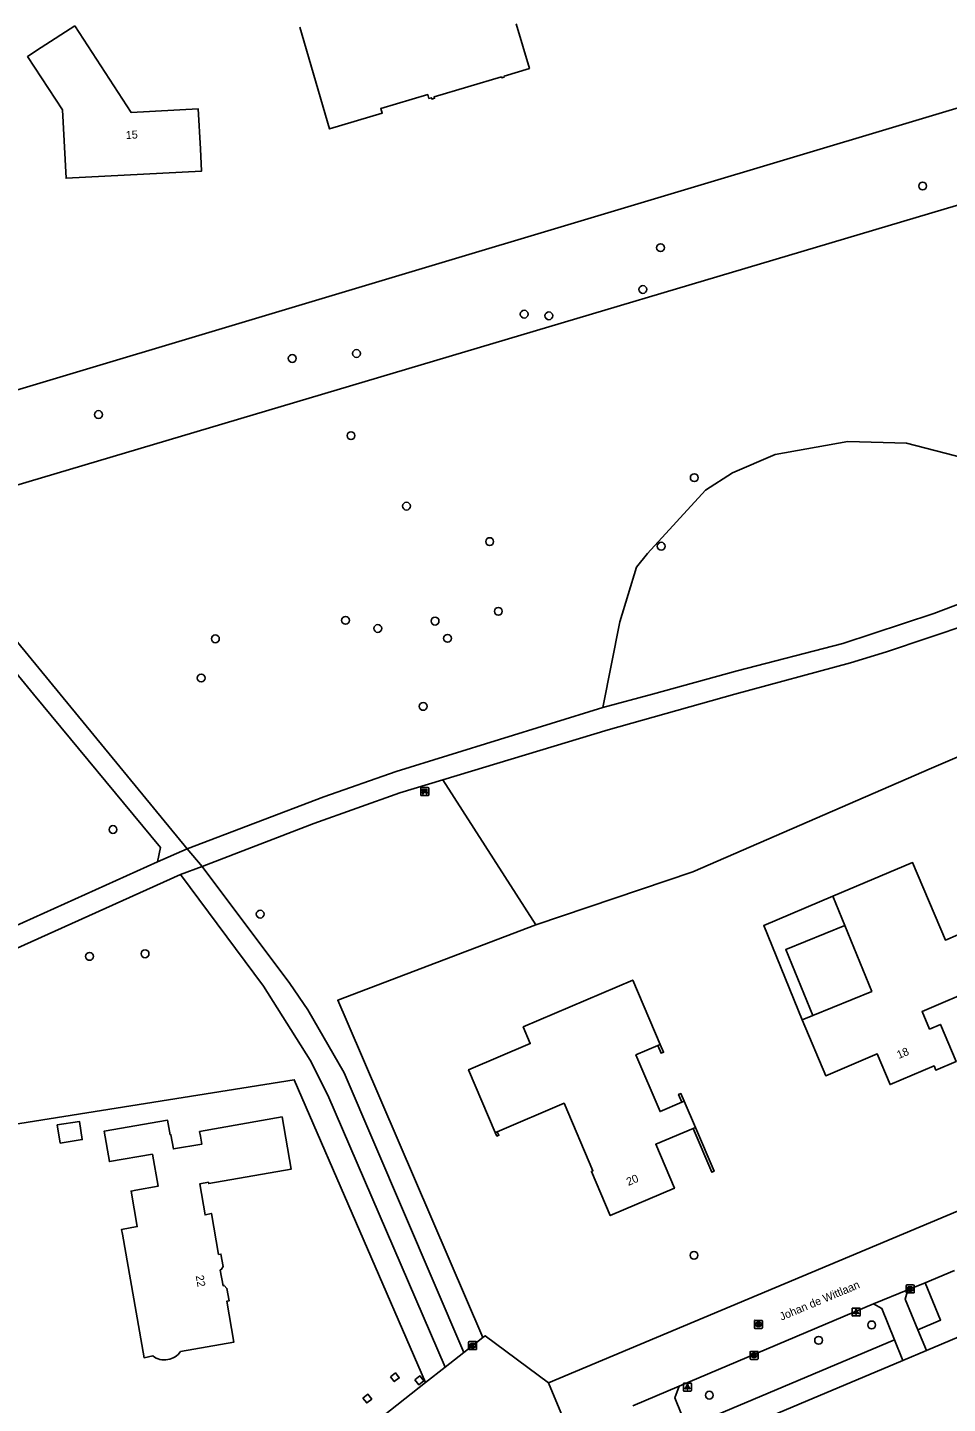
# Model space of a CAD drawing. Extents: x 162417 to 163721, y 384268 to 385416.
# Drawn here: x 163118.6 to 163233.5, y 384911.4 to 385083.3 of the extents above; entities that cross this region are included whole.
import ezdxf

# ---------------------------------------------------------------- set-up
doc = ezdxf.new("R2010")
doc.units = 0
for name, color, linetype in [('IMGEO_Bank', 7, 'Continuous'), ('IMGEO_Boom', 7, 'Continuous'), ('IMGEO_Erf', 7, 'Continuous'), ('IMGEO_Gemengd_bos', 7, 'Continuous'), ('IMGEO_Groenvoorziening', 7, 'Continuous'), ('IMGEO_Kolk', 7, 'Continuous'), ('IMGEO_Lichtpunt', 7, 'Continuous'), ('IMGEO_Loofbos', 7, 'Continuous'), ('IMGEO_Muur', 7, 'Continuous'), ('IMGEO_Openbare_ruimte_label', 7, 'Continuous'), ('IMGEO_Pand', 7, 'Continuous'), ('IMGEO_Pand_nummerreeks', 7, 'Continuous'), ('IMGEO_Pand_vergunning_verleend', 7, 'Continuous'), ('IMGEO_Rijbaan_lokaal_gesloten', 7, 'Continuous'), ('IMGEO_Rioolput', 7, 'Continuous'), ('IMGEO_Voetpad_halfverhard', 7, 'Continuous'), ('IMGEO_Voetpad_open', 7, 'Continuous')]:
    doc.layers.add(name, color=color, linetype=linetype)

msp = doc.modelspace()

# ---------------------------------------------------------------- linework, layer by layer
at = {"layer": 'IMGEO_Bank'}
for p, q in [((163167.7, 384987.41), (163167.7, 384988.25)), ((163167.7, 384988.25), (163167.7, 384987.41)), ((163167.78, 384988.34), (163168.62, 384988.34)), ((163168.62, 384988.34), (163167.78, 384988.34)), ((163168.63, 384987.34), (163167.79, 384987.34)), ((163167.79, 384987.34), (163168.63, 384987.34)), ((163168.01, 384987.85), (163168.01, 384987.95)), ((163168.4, 384987.74), (163168.01, 384987.74)), ((163168.34, 384987.96), (163168.06, 384987.96)), ((163168.06, 384987.95), (163168.06, 384987.85)), ((163168.06, 384987.84), (163168.34, 384987.84)), ((163168.35, 384987.85), (163168.35, 384987.95)), ((163168.39, 384987.95), (163168.39, 384987.85)), ((163168.7, 384988.26), (163168.7, 384987.42)), ((163168.7, 384987.42), (163168.7, 384988.26))]:
    msp.add_line(p, q, dxfattribs=at)
for points in [[(163167.95, 384987.74), (163167.81, 384987.74), (163167.92, 384987.84), (163168.01, 384987.84)], [(163168.01, 384987.96), (163167.92, 384987.96), (163167.92, 384988.12), (163168.48, 384988.12), (163168.48, 384987.96), (163168.4, 384987.96)], [(163168, 384987.73), (163168, 384987.52), (163167.96, 384987.52), (163167.96, 384987.73)], [(163168.4, 384987.84), (163168.48, 384987.84), (163168.6, 384987.74), (163168.46, 384987.74)], [(163168.45, 384987.73), (163168.45, 384987.52), (163168.41, 384987.52), (163168.41, 384987.73)]]:
    msp.add_lwpolyline(points, dxfattribs=at)
for centre, radius, start, end in [((163167.78, 384988.26), 0.0779, 92.4484, 184.2845), ((163167.78, 384988.26), 0.0779, 92.4484, 184.2845), ((163167.78, 384987.42), 0.0779, 182.4484, 274.2845), ((163167.78, 384987.42), 0.0779, 182.4484, 274.2845), ((163167.95, 384987.73), 0.00671, 2.8957, 87.1043), ((163168.01, 384987.73), 0.00671, 92.8957, 177.1043), ((163168.01, 384987.95), 0.00671, 2.8957, 87.1043), ((163168.01, 384987.85), 0.00671, 272.8957, 357.1043), ((163168.06, 384987.95), 0.00671, 92.8957, 177.1043), ((163168.06, 384987.85), 0.00671, 182.8957, 267.1043), ((163168.34, 384987.95), 0.00671, 2.8957, 87.1043), ((163168.34, 384987.85), 0.00671, 272.8957, 357.1043), ((163168.4, 384987.95), 0.00671, 92.8957, 177.1043), ((163168.4, 384987.85), 0.00671, 182.8957, 267.1043), ((163168.4, 384987.73), 0.00671, 2.8957, 87.1043), ((163168.46, 384987.73), 0.00671, 92.8957, 177.1043), ((163168.63, 384988.26), 0.0779, 2.4484, 94.2845), ((163168.63, 384988.26), 0.0779, 2.4484, 94.2845), ((163168.63, 384987.42), 0.0779, 272.4484, 4.2845), ((163168.63, 384987.42), 0.0779, 272.4484, 4.2845)]:
    msp.add_arc(centre, radius, start, end, dxfattribs=at)
at = {"layer": 'IMGEO_Boom'}
for centre in [(163230.43, 385063.49), (163197.68, 385055.79), (163195.47, 385050.57), (163180.64, 385047.48), (163183.72, 385047.28), (163151.65, 385041.95), (163159.68, 385042.57), (163127.44, 385034.94), (163158.99, 385032.31), (163201.89, 385027.05), (163165.93, 385023.5), (163176.32, 385019.07), (163197.76, 385018.49), (163158.31, 385009.23), (163169.5, 385009.14), (163177.4, 385010.36), (163162.34, 385008.22), (163142.05, 385006.93), (163171.06, 385006.98), (163140.27, 385002.03), (163168.02, 384998.48), (163129.25, 384983.1), (163147.65, 384972.53), (163126.32, 384967.25), (163133.26, 384967.58), (163201.86, 384929.91), (163224.06, 384921.21), (163217.43, 384919.29), (163203.78, 384912.43)]:
    msp.add_circle(centre, 0.489, dxfattribs=at)
at = {"layer": 'IMGEO_Erf'}
for points in [[(163215.38, 384959.32), (163210.57, 384971.11), (163219.21, 384974.77)], [(163216.7, 384959.86), (163213.33, 384968.12), (163220.69, 384971.13)], [(163163.93, 384914.74), (163164.55, 384915.21), (163165.02, 384914.6), (163164.4, 384914.13), (163163.93, 384914.74)], [(163166.99, 384914.36), (163167.6, 384914.84), (163168.09, 384914.23), (163167.47, 384913.74), (163166.99, 384914.36)], [(163160.49, 384912.08), (163161.1, 384912.56), (163161.58, 384911.94), (163160.97, 384911.47), (163160.49, 384912.08)]]:
    msp.add_lwpolyline(points, dxfattribs=at)
at = {"layer": 'IMGEO_Gemengd_bos'}
for points in [[(163109.64, 385035.76), (163200.68, 385063.02), (163281.97, 385087.41)], [(163104.31, 385022.27), (163286.02, 385076.36)], [(163277.36, 385010.29), (163269.66, 385007.07), (163253.07, 385000), (163231.53, 384990.76), (163201.72, 384977.8), (163182.1, 384971.2)], [(163170.48, 384989.3), (163182.1, 384971.2)], [(163182.1, 384971.2), (163157.34, 384961.78), (163158.51, 384959.07), (163175.47, 384919.62)]]:
    msp.add_lwpolyline(points, dxfattribs=at)
at = {"layer": 'IMGEO_Groenvoorziening'}
msp.add_lwpolyline([(163190.46, 384998.35), (163192.6, 385009.04), (163194.69, 385015.88), (163196.06, 385017.57), (163203.31, 385025.48), (163206.68, 385027.67), (163212, 385029.94), (163221.1, 385031.58), (163228.41, 385031.37), (163249.98, 385025.8), (163256.09, 385024.66), (163270.81, 385024.87)], dxfattribs=at)
at = {"layer": 'IMGEO_Kolk'}
for p, q in [((163228.38, 384925.28), (163228.38, 384926.13)), ((163228.46, 384926.21), (163229.31, 384926.21)), ((163228.87, 384925.99), (163228.89, 384925.99)), ((163228.89, 384925.43), (163228.87, 384925.43)), ((163229.38, 384926.13), (163229.38, 384925.28)), ((163229.31, 384925.21), (163228.46, 384925.21)), ((163173.69, 384918.2), (163173.69, 384919.05)), ((163173.76, 384919.13), (163174.62, 384919.13)), ((163174.18, 384918.91), (163174.2, 384918.91)), ((163174.69, 384919.05), (163174.69, 384918.2)), ((163174.62, 384918.13), (163173.76, 384918.13)), ((163174.2, 384918.35), (163174.18, 384918.35)), ((163208.86, 384916.99), (163208.86, 384917.84)), ((163208.94, 384917.91), (163209.79, 384917.91)), ((163209.79, 384916.91), (163208.94, 384916.91)), ((163209.35, 384917.69), (163209.38, 384917.69)), ((163209.37, 384917.13), (163209.35, 384917.13)), ((163209.86, 384917.84), (163209.86, 384916.99))]:
    msp.add_line(p, q, dxfattribs=at)
for points in [[(163228.38, 384925.28), (163228.38, 384926.13)], [(163228.46, 384926.21), (163229.31, 384926.21)], [(163228.7, 384925.91), (163228.83, 384925.91), (163228.83, 384925.76), (163228.95, 384925.91), (163229.12, 384925.91), (163228.97, 384925.76), (163229.13, 384925.51), (163228.97, 384925.51), (163228.89, 384925.67), (163228.83, 384925.6), (163228.83, 384925.51), (163228.7, 384925.51), (163228.7, 384925.91)], [(163229.38, 384926.13), (163229.38, 384925.28)], [(163229.31, 384925.21), (163228.46, 384925.21)], [(163173.69, 384918.2), (163173.69, 384919.05)], [(163173.76, 384919.13), (163174.62, 384919.13)], [(163174.01, 384918.83), (163174.13, 384918.83), (163174.13, 384918.67), (163174.26, 384918.83), (163174.43, 384918.83), (163174.28, 384918.68), (163174.43, 384918.43), (163174.28, 384918.43), (163174.2, 384918.59), (163174.13, 384918.52), (163174.13, 384918.43), (163174.01, 384918.43), (163174.01, 384918.83)], [(163174.69, 384919.05), (163174.69, 384918.2)], [(163174.62, 384918.13), (163173.76, 384918.13)], [(163208.86, 384916.99), (163208.86, 384917.84)], [(163208.94, 384917.91), (163209.79, 384917.91)], [(163209.79, 384916.91), (163208.94, 384916.91)], [(163209.18, 384917.61), (163209.31, 384917.61), (163209.31, 384917.46), (163209.44, 384917.61), (163209.6, 384917.61), (163209.45, 384917.46), (163209.61, 384917.21), (163209.45, 384917.21), (163209.37, 384917.38), (163209.31, 384917.31), (163209.31, 384917.21), (163209.18, 384917.21), (163209.18, 384917.61)], [(163209.86, 384917.84), (163209.86, 384916.99)]]:
    msp.add_lwpolyline(points, dxfattribs=at)
for centre, start, end in [((163228.46, 384926.13), 91.552, 178.448), ((163228.46, 384926.13), 91.552, 178.448), ((163229.31, 384926.13), 1.552, 88.448), ((163229.31, 384926.13), 1.552, 88.448), ((163228.46, 384925.28), 181.552, 268.448), ((163228.46, 384925.28), 181.552, 268.448), ((163229.31, 384925.28), 271.552, 358.448), ((163229.31, 384925.28), 271.552, 358.448), ((163173.77, 384919.05), 91.552, 178.448), ((163173.77, 384919.05), 91.552, 178.448), ((163174.61, 384919.05), 1.552, 88.448), ((163174.61, 384919.05), 1.552, 88.448), ((163173.77, 384918.2), 181.552, 268.448), ((163173.77, 384918.2), 181.552, 268.448), ((163174.61, 384918.2), 271.552, 358.448), ((163174.61, 384918.2), 271.552, 358.448), ((163208.94, 384917.84), 91.552, 178.448), ((163208.94, 384917.84), 91.552, 178.448), ((163208.94, 384916.99), 181.552, 268.448), ((163208.94, 384916.99), 181.552, 268.448), ((163209.79, 384917.84), 1.552, 88.448), ((163209.79, 384917.84), 1.552, 88.448), ((163209.79, 384916.99), 271.552, 358.448), ((163209.79, 384916.99), 271.552, 358.448)]:
    msp.add_arc(centre, 0.0765, start, end, dxfattribs=at)
for centre, major_axis, ratio, start_param, end_param in [((163228.87, 384925.71), (-0.387, 0.002), 0.722429, 4.712389, 7.853982), ((163228.89, 384925.71), (-0.39, 0.002), 0.717154, 1.570796, 4.712389), ((163174.18, 384918.63), (-0.387, 0.002), 0.722429, 4.712389, 7.853982), ((163174.2, 384918.63), (-0.39, 0.002), 0.717154, 1.570796, 4.712389), ((163209.35, 384917.41), (-0.387, 0.002), 0.722429, 4.712389, 7.853982), ((163209.37, 384917.41), (-0.39, 0.002), 0.717154, 1.570796, 4.712389)]:
    msp.add_ellipse(centre, major_axis=major_axis, ratio=ratio, start_param=start_param, end_param=end_param, dxfattribs=at)
at = {"layer": 'IMGEO_Lichtpunt'}
for p, q in [((163221.62, 384923.23), (163221.62, 384922.42)), ((163221.62, 384923.23), (163221.62, 384922.42)), ((163222.52, 384923.32), (163221.71, 384923.32)), ((163222.52, 384923.32), (163221.71, 384923.32)), ((163221.71, 384922.33), (163222.52, 384922.33)), ((163221.71, 384922.33), (163222.52, 384922.33)), ((163222.61, 384922.42), (163222.61, 384923.23)), ((163222.61, 384922.42), (163222.61, 384923.23)), ((163200.54, 384913.85), (163200.54, 384913.04)), ((163200.54, 384913.85), (163200.54, 384913.04)), ((163201.44, 384913.94), (163200.63, 384913.94)), ((163201.44, 384913.94), (163200.63, 384913.94)), ((163201.53, 384913.04), (163201.53, 384913.85)), ((163201.53, 384913.04), (163201.53, 384913.85)), ((163200.63, 384912.95), (163201.44, 384912.95)), ((163200.63, 384912.95), (163201.44, 384912.95))]:
    msp.add_line(p, q, dxfattribs=at)
for points in [[(163221.99, 384922.89), (163222.03, 384922.86), (163221.84, 384922.6), (163221.8, 384922.63), (163221.99, 384922.89)], [(163222.09, 384922.84), (163222.14, 384922.84), (163222.14, 384922.52), (163222.09, 384922.52), (163222.09, 384922.84)], [(163222.2, 384922.86), (163222.24, 384922.89), (163222.43, 384922.63), (163222.39, 384922.6), (163222.2, 384922.86)], [(163200.91, 384913.51), (163200.95, 384913.49), (163200.76, 384913.22), (163200.72, 384913.25), (163200.91, 384913.51)], [(163201.01, 384913.47), (163201.06, 384913.47), (163201.06, 384913.14), (163201.01, 384913.14), (163201.01, 384913.47)], [(163201.12, 384913.49), (163201.16, 384913.51), (163201.35, 384913.25), (163201.31, 384913.22), (163201.12, 384913.49)]]:
    msp.add_lwpolyline(points, dxfattribs=at)
for centre in [(163222.12, 384923.03), (163201.04, 384913.65)]:
    msp.add_circle(centre, 0.0994, dxfattribs=at)
for centre, start, end in [((163221.71, 384923.23), 90, 180), ((163221.71, 384923.23), 90, 180), ((163221.71, 384922.42), 180, 270), ((163221.71, 384922.42), 180, 270), ((163222.52, 384923.23), 0, 90), ((163222.52, 384923.23), 0, 90), ((163222.52, 384922.42), 270, 0), ((163222.52, 384922.42), 270, 360), ((163200.63, 384913.85), 90, 180), ((163200.63, 384913.85), 90, 180), ((163201.44, 384913.85), 0, 90), ((163201.44, 384913.85), 0, 90), ((163200.63, 384913.04), 180, 270), ((163200.63, 384913.04), 180, 270), ((163201.44, 384913.04), 270, 0), ((163201.44, 384913.04), 270, 360)]:
    msp.add_arc(centre, 0.0946, start, end, dxfattribs=at)
at = {"layer": 'IMGEO_Loofbos'}
msp.add_lwpolyline([(163168.29, 384914), (163151.9, 384951.84), (163097.15, 384943.13), (163103.62, 384899.24), (163109.03, 384862.7), (163116.8, 384810.17), (163172.67, 384818.52)], dxfattribs=at)
at = {"layer": 'IMGEO_Muur'}
for points in [[(163197.34, 384956.11), (163197.75, 384955.15), (163198.05, 384955.27), (163197.64, 384956.24)], [(163200.64, 384949.16), (163200.23, 384950.12), (163199.94, 384950), (163200.35, 384949.03)], [(163177.03, 384945.23), (163177.22, 384944.8), (163177.47, 384944.91), (163177.28, 384945.34)], [(163201.74, 384945.76), (163204.07, 384940.29), (163204.37, 384940.42), (163202.04, 384945.89)]]:
    msp.add_lwpolyline(points, dxfattribs=at)
at = {"layer": 'IMGEO_Pand'}
for points in [[(163124.48, 385083.5), (163131.52, 385072.68), (163139.91, 385073.12), (163140.17, 385068.13), (163140.32, 385065.36), (163123.38, 385064.46), (163122.93, 385072.99), (163118.58, 385079.67), (163120.29, 385080.78), (163124.48, 385083.5)], [(163179.64, 385083.75), (163181.3, 385078.18), (163178.14, 385077.23), (163178.17, 385077.12), (163177.83, 385077.02), (163177.8, 385077.13), (163169.38, 385074.63), (163169.43, 385074.46), (163169.08, 385074.36), (163169.04, 385074.52), (163168.73, 385074.43), (163168.58, 385074.91), (163162.72, 385073.16), (163162.89, 385072.59), (163156.31, 385070.62), (163152.58, 385083.32)], [(163219.21, 384974.77), (163229.17, 384978.98), (163233.27, 384969.28), (163234.83, 384969.94), (163237.58, 384963.43), (163230.37, 384960.38), (163231.3, 384958.18), (163232.66, 384958.75), (163234.62, 384954.11), (163232.08, 384953.04), (163231.86, 384953.56), (163226.37, 384951.24), (163224.75, 384955.07), (163218.33, 384952.35), (163215.38, 384959.32)], [(163219.21, 384974.77), (163220.69, 384971.13)], [(163220.69, 384971.13), (163224.07, 384962.87), (163216.7, 384959.86)], [(163197.64, 384956.24), (163194.21, 384964.29), (163180.51, 384958.45), (163181.4, 384956.36), (163173.69, 384953.08), (163177.03, 384945.23)], [(163216.7, 384959.86), (163215.38, 384959.32)], [(163200.35, 384949.03), (163197.62, 384947.87), (163194.61, 384954.95), (163197.34, 384956.11)], [(163197.64, 384956.24), (163197.34, 384956.11)], [(163177.28, 384945.34), (163185.63, 384948.9), (163189.22, 384940.47), (163189.04, 384940.39), (163191.39, 384934.87), (163199.42, 384938.29), (163197.08, 384943.78), (163201.74, 384945.76)], [(163200.35, 384949.03), (163200.64, 384949.16)], [(163202.04, 384945.89), (163200.64, 384949.16)], [(163134.24, 384917.33), (163133.14, 384917.12), (163130.43, 384932.54), (163130.32, 384933.15), (163132.29, 384933.5), (163131.51, 384937.93), (163132.11, 384938.04), (163134.89, 384938.53), (163134.18, 384942.53), (163128.8, 384941.61), (163128.15, 384945.42), (163136.08, 384946.78), (163136.39, 384944.96), (163136.49, 384944.98), (163136.8, 384943.19), (163140.34, 384943.79), (163140.17, 384944.78), (163140.07, 384945.37), (163150.39, 384947.19), (163151.53, 384940.69), (163141.21, 384938.87), (163141.17, 384939.03), (163140.11, 384938.85), (163140.76, 384934.95), (163141.54, 384935.14), (163142.45, 384930.01), (163142.74, 384930.06), (163143.02, 384928.53), (163142.83, 384928.17), (163142.66, 384928.06), (163143.01, 384926.11), (163143.16, 384926.14), (163143.49, 384925.78), (163143.77, 384924.23), (163143.48, 384924.2), (163144.36, 384919.07), (163137.7, 384917.91)], [(163177.28, 384945.34), (163177.03, 384945.23)], [(163202.04, 384945.89), (163201.74, 384945.76)]]:
    msp.add_lwpolyline(points, dxfattribs=at)
msp.add_arc((163135.7, 384919.24), 2.4, 232.4077, 326.3293, dxfattribs=at)
at = {"layer": 'IMGEO_Pand_vergunning_verleend'}
msp.add_lwpolyline([(163122.29, 384946.2), (163125.05, 384946.64), (163125.41, 384944.37), (163122.66, 384943.93), (163122.29, 384946.2)], dxfattribs=at)
at = {"layer": 'IMGEO_Rijbaan_lokaal_gesloten'}
for points in [[(163183.67, 384913.96), (163328.96, 384974.96)], [(163230.74, 384926.48), (163234.4, 384928)], [(163224.3, 384923.83), (163228.59, 384925.58)], [(163228.59, 384925.58), (163230.74, 384926.48)], [(163200.02, 384913.55), (163224.3, 384923.83)], [(163173.11, 384917.78), (163175.47, 384919.62)], [(163175.47, 384919.62), (163175.76, 384919.85), (163183.67, 384913.96)], [(163170.76, 384915.95), (163173.11, 384917.78)], [(163168.29, 384914), (163170.76, 384915.95)], [(163172.67, 384818.52), (163159.56, 384907.09), (163168.29, 384914)], [(163183.67, 384913.96), (163186.27, 384907.76)], [(163194.23, 384911.1), (163200.02, 384913.55)]]:
    msp.add_lwpolyline(points, dxfattribs=at)
at = {"layer": 'IMGEO_Rioolput'}
for p, q in [((163209.42, 384920.86), (163209.42, 384921.71)), ((163209.49, 384921.78), (163210.34, 384921.78)), ((163210.34, 384920.78), (163209.49, 384920.78)), ((163209.9, 384921.56), (163209.93, 384921.56)), ((163209.93, 384921), (163209.9, 384921)), ((163210.42, 384921.71), (163210.42, 384920.86))]:
    msp.add_line(p, q, dxfattribs=at)
for points in [[(163209.42, 384920.86), (163209.42, 384921.71)], [(163209.49, 384921.78), (163210.34, 384921.78)], [(163210.34, 384920.78), (163209.49, 384920.78)], [(163210, 384921.48), (163209.75, 384921.48), (163209.75, 384921.08)], [(163209.75, 384921.08), (163209.88, 384921.08), (163209.88, 384921.25), (163209.89, 384921.25)], [(163209.93, 384921.4), (163209.88, 384921.4), (163209.88, 384921.32)], [(163209.88, 384921.32), (163209.93, 384921.32)], [(163209.93, 384921.22), (163210.01, 384921.08), (163210.14, 384921.08), (163210.08, 384921.21)], [(163210.42, 384921.71), (163210.42, 384920.86)]]:
    msp.add_lwpolyline(points, dxfattribs=at)
for centre, radius, start, end in [((163209.49, 384921.71), 0.0765, 91.552, 178.448), ((163209.49, 384921.71), 0.0765, 91.552, 178.448), ((163209.49, 384920.86), 0.0765, 181.552, 268.448), ((163209.49, 384920.86), 0.0765, 181.552, 268.448), ((163209.89, 384921.19), 0.0533, 26.0293, 88.6989), ((163209.94, 384921.31), 0.0964, 77.0061, 93.1865), ((163209.91, 384921.51), 0.19, 274.7715, 282.9687), ((163209.95, 384921.36), 0.0378, 276.6634, 79.6772), ((163210, 384921.37), 0.109, 350.3612, 89.416), ((163210, 384921.37), 0.112, 277.5842, 350.9817), ((163209.99, 384921.16), 0.108, 29.5134, 73.7905), ((163210.34, 384921.71), 0.0765, 1.552, 88.448), ((163210.34, 384921.71), 0.0765, 1.552, 88.448), ((163210.34, 384920.86), 0.0765, 271.552, 358.448), ((163210.34, 384920.86), 0.0765, 271.552, 358.448)]:
    msp.add_arc(centre, radius, start, end, dxfattribs=at)
for centre, major_axis, ratio, start_param, end_param in [((163209.9, 384921.28), (-0.387, 0.002), 0.722429, 4.712389, 7.853982), ((163209.93, 384921.28), (-0.39, 0.002), 0.717154, 1.570796, 4.712389)]:
    msp.add_ellipse(centre, major_axis=major_axis, ratio=ratio, start_param=start_param, end_param=end_param, dxfattribs=at)
at = {"layer": 'IMGEO_Voetpad_halfverhard'}
for points in [[(163022.25, 385155.33), (163026.36, 385140.66), (163030.88, 385128.65), (163034.75, 385119.33), (163043.02, 385103.45), (163046.25, 385098.24), (163062.55, 385073.53), (163064.94, 385070.15), (163071.17, 385061.92), (163077.11, 385053.26), (163082.23, 385046.23), (163093.91, 385030.98), (163094.01, 385030.86), (163119.33, 385000), (163135.19, 384980.85), (163134.8, 384979.05)], [(163270.81, 385024.87), (163231.85, 385010.07), (163220.47, 385006.34), (163207.26, 385002.94), (163196.67, 385000), (163190.46, 384998.35)], [(163104.31, 385022.27), (163122.66, 385000), (163138.54, 384980.68)], [(163264.45, 385019.53), (163236.32, 385008.78), (163225.93, 385005.28), (163221.42, 385003.91), (163206.97, 385000), (163191.13, 384995.57), (163170.48, 384989.3)], [(163138.54, 384980.68), (163155.6, 384987.18), (163164.64, 384990.34), (163190.46, 384998.35)], [(163170.48, 384989.3), (163165.11, 384987.68), (163154.34, 384983.85), (163140.38, 384978.5)], [(163134.8, 384979.05), (163138.54, 384980.68)], [(163138.54, 384980.68), (163140.38, 384978.5)], [(163134.8, 384979.05), (163110.23, 384967.99), (163092.28, 384959.6), (163086.1, 384956.95), (163066.48, 384948.01), (163056.27, 384942.95)], [(163137.67, 384977.49), (163065.94, 384945.15), (163057.3, 384940.82), (163048.98, 384936.04)], [(163140.38, 384978.5), (163137.67, 384977.49)], [(163170.76, 384915.95), (163156.09, 384949.92), (163153.91, 384954.28), (163148.07, 384963.52), (163137.67, 384977.49)], [(163140.38, 384978.5), (163151.33, 384963.85), (163153.6, 384960.57), (163158.12, 384952.7), (163173.11, 384917.78)]]:
    msp.add_lwpolyline(points, dxfattribs=at)
at = {"layer": 'IMGEO_Voetpad_open'}
for points in [[(163305.95, 384950.1), (163301.52, 384948.92), (163287.11, 384942.95), (163279.76, 384939.57), (163273.18, 384936.42), (163263.16, 384931.62), (163230.9, 384918.02)], [(163229.82, 384920.6), (163228.23, 384924.43), (163228.59, 384925.58)], [(163230.74, 384926.48), (163232.68, 384921.82), (163229.82, 384920.6)], [(163224.3, 384923.83), (163225.35, 384923.27), (163226.91, 384919.36)], [(163229.82, 384920.6), (163230.9, 384918.02)], [(163226.91, 384919.36), (163200.97, 384908.41)], [(163226.91, 384919.36), (163227.94, 384916.77)], [(163227.94, 384916.77), (163202.03, 384905.85)], [(163230.9, 384918.02), (163227.94, 384916.77)], [(163200.97, 384908.41), (163199.45, 384912.09), (163200.02, 384913.55)]]:
    msp.add_lwpolyline(points, dxfattribs=at)

# ---------------------------------------------------------------- texts
at = {"layer": 'IMGEO_Openbare_ruimte_label'}
msp.add_text('Johan de Wittlaan', height=1, rotation=22.7697, dxfattribs=at).set_placement((163212.8, 384921.73))
at = {"layer": 'IMGEO_Pand_nummerreeks'}
for s, rotation, p in [('15', 3.0458, (163130.88, 385069.36)), ('18', 22.9069, (163227.46, 384954.43)), ('20', 23.0616, (163193.66, 384938.57)), ('22', 279.9864, (163139.58, 384927.35))]:
    msp.add_text(s, height=1, rotation=rotation, dxfattribs=at).set_placement(p)

doc.saveas('drawing.dxf')
